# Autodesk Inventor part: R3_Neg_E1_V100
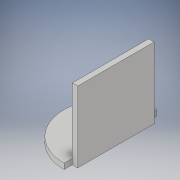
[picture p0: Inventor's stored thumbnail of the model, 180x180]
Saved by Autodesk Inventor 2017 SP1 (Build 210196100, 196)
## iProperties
Part Number: R3_Neg_E1_V100
Material: Generisch
Document SubType Name: Modeling
Designer: haesner
Density: 1 g/cm^3
Appearance: Vorgabe
Part Number: R_Negativ_Cover_v1-1_3D-Druck
Author: haesner
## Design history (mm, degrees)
sketch "Skizze2"
  geometry: L1 (0, -23.8)-(0, 23.8) reference; L2 (0, 17)-(0, -17); A1 r 17 centre (0, 0) between (0, 17) and (0, -17); 1 further point
  constraints: 2 end point, 2 point on circle, 2 point on line, 1 centre point, 1 coincident, 1 collinear
  dimensions: "d3" = 17 radius of A1
extrude "Extrusion2" new body sketch "Skizze2" distance "d4" = 2; taper "d5" = 0 deg
sketch "Skizze3"
  geometry: L1 (0, -17)-(0, 17) reference; L2 (0, 8.5)-(0, -8.5); A1 r 8.5 centre (0, 0) between (0, 8.5) and (0, -8.5); 1 further point
  constraints: 2 end point, 2 point on circle, 1 centre point, 1 coincident, 1 point on line, 1 vertical
  dimensions: "d6" = 8.5 radius of A1
extrude "Extrusion3" join sketch "Skizze3" distance "d7" = 21; taper "d8" = 0 deg
workplane "Arbeitsebene1"
feature "Trennen1"
sketch "Skizze4"
  geometry: L1 (0, 3)-(-26, 3); L2 (-26, 3)-(-26, 31); L3 (-26, 31)-(0, 31); L4 (0, 31)-(0, 3); L5 (0, -6.8)-(0, 40.8) reference; L6 (4.8, 17)-(-28.8, 17) reference
  constraints: 8 end point, 1 collinear, 1 horizontal, 1 parallel, 1 perpendicular, 1 other
  dimensions: "d10" = 26 distance of L3.end L2.end; "d13" = 28 distance between parallel lines of L1 L3
extrude "Extrusion4" join sketch "Skizze4" distance "d11" = 2; taper "d12" = 0 deg
node "Volumenkörper2"
other parameters: "d9" = -40 deg
